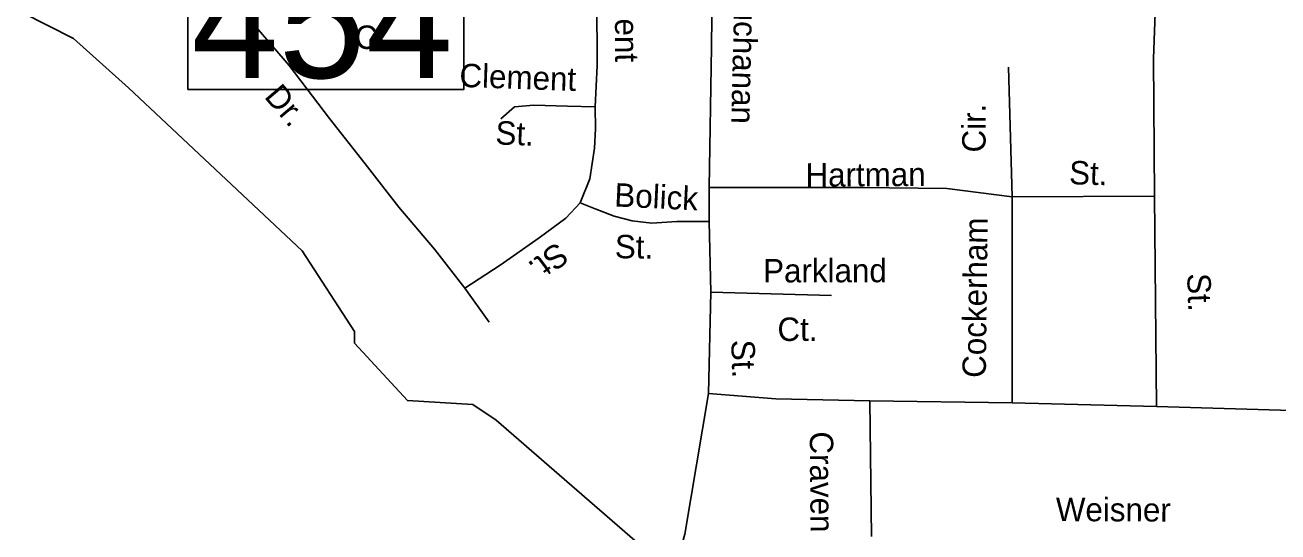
# Model space of a CAD drawing. Extents: x 1551653 to 1702041, y 811336 to 920032.
# Drawn here: x 1628058 to 1631566, y 842302 to 843721 of the extents above; entities that cross this region are included whole.
import ezdxf

# ---------------------------------------------------------------- set-up
doc = ezdxf.new("R2010")
doc.units = 0
for name, color, linetype in [('Old_Level_10', 7, 'Continuous'), ('Old_Level_31', 7, 'Continuous'), ('Old_Level_35', 7, 'Continuous'), ('Old_Level_59', 7, 'Continuous')]:
    doc.layers.add(name, color=color, linetype=linetype)

msp = doc.modelspace()

# ---------------------------------------------------------------- linework, layer by layer
at = {"layer": 'Old_Level_31'}
msp.add_lwpolyline([(1628514.011, 843909.718), (1629286.946, 843909.718), (1629286.946, 843540.573), (1628514.011, 843540.573), (1628514.011, 843909.718)], dxfattribs=at)
at = {"layer": 'Old_Level_35'}
for p, q in [((1630811.709, 843603.048), (1630822.146, 843240.118)), ((1629973.936, 843265.908), (1629973.936, 843170.456)), ((1631220.942, 843241.89), (1630822.146, 843240.118)), ((1630822.146, 843240.118), (1630822.146, 842663.086)), ((1631220.942, 843241.89), (1631226.827, 842652.777)), ((1629973.936, 843170.456), (1629978.478, 842972.733)), ((1629289.34, 842984.266), (1629357.851, 842889.224)), ((1629978.478, 842972.733), (1629972.071, 842689.655)), ((1629978.478, 842972.733), (1630316.803, 842963.643)), ((1630822.146, 842663.086), (1630423.788, 842668.615)), ((1630423.788, 842668.615), (1630427.939, 842289.151)), ((1631226.827, 842652.777), (1630822.146, 842663.086))]:
    msp.add_line(p, q, dxfattribs=at)
for points in [[(1631306.723, 844441.237), (1631254.718, 844311.16), (1631233.844, 844060.503), (1631218.19, 843627.076), (1631220.942, 843241.89)], [(1629663.72, 844087.889), (1629660.373, 843991.902), (1629659.359, 843794.012), (1629660.389, 843608.09), (1629654.638, 843492.342)], [(1629985.29, 844078.246), (1629980.748, 843660.074), (1629973.936, 843265.908)], [(1628550.243, 844054.865), (1628567.179, 843936.226), (1628594.275, 843854.873), (1628631.533, 843804.027), (1628665.756, 843760.941), (1628797.31, 843607.188), (1628910.978, 843459.603), (1629010.847, 843332.106), (1629105.033, 843210.729), (1629205.108, 843093.432), (1629289.34, 842984.266)], [(1629654.638, 843492.342), (1629576.82, 843493.52), (1629482.837, 843496.827), (1629428.904, 843491.719), (1629390.406, 843458.281)], [(1629654.638, 843492.342), (1629655.78, 843430.282), (1629652.889, 843376.513), (1629639.743, 843290.732), (1629612.558, 843223.245)], [(1629973.936, 843265.908), (1630398.546, 843265.908), (1630639.234, 843263.635), (1630822.146, 843240.118)], [(1629289.34, 842984.266), (1629388.3, 843048.695), (1629497.306, 843124.928), (1629572.056, 843179.843), (1629612.558, 843223.245)], [(1629612.558, 843223.245), (1629654.445, 843206.585), (1629708.05, 843185.686), (1629757.82, 843173.071), (1629813.509, 843166.139), (1629883.647, 843171.119), (1629973.936, 843170.456)], [(1629972.071, 842689.655), (1629905.451, 842295.18), (1629802.746, 841928.486), (1629744.453, 841720.135), (1629636.197, 841517.342), (1629534.011, 841383.711), (1629450.736, 841294.815), (1629361.91, 841230.921), (1629256.429, 841155.915), (1629148.172, 841058.685), (1629074.232, 840958.229)], [(1629972.071, 842689.655), (1630160.173, 842674.135), (1630423.788, 842668.615)], [(1632385.28, 842629.31), (1631986.622, 842631.657), (1631637.21, 842641.043), (1631226.827, 842652.777)]]:
    msp.add_lwpolyline(points, dxfattribs=at)
at = {"layer": 'Old_Level_59'}
for points in [[(1629377.791, 842615.042), (1629311.764, 842659.025), (1629128.755, 842669.381), (1628980.81, 842829.936), (1628980.81, 842862.745), (1628833.788, 843088.917), (1628347.814, 843545.261), (1628194.141, 843682.91), (1627906.967, 843829.064), (1627480.777, 843939.956), (1627148.828, 844132.132), (1626891.73, 844063.731)], [(1630570.066, 840506.44), (1630486.815, 840718.208), (1630466.822, 841119.084), (1630403.769, 841419.024), (1630183.851, 841781.351), (1629814.757, 842235.234), (1629377.791, 842615.042)]]:
    msp.add_lwpolyline(points, dxfattribs=at)

# ---------------------------------------------------------------- texts
at = {"layer": 'Old_Level_10'}
for s, rotation, p in [('Clement', 270.317469, (1629708.897, 843943.81)), ('Buchanan', 268.610667, (1630045.154, 843839.85)), ('Ct.', 359.876581, (1628981.447, 843654.116)), ('Clement', 357.984697, (1629273.689, 843547.77)), ('Dr.', 310.470247, (1628725.771, 843519.558)), ('Cir.', 89.930389, (1630747.862, 843364.109)), ('St.', 357.984697, (1629374.583, 843386.866)), ('St.', 358.379758, (1630981.095, 843275.341)), ('Hartman', 0.300303, (1630243.713, 843268.544)), ('Bolick', 357.232975, (1629707.152, 843213.203)), ('Cockerham', 89.31545, (1630748.395, 842732.973)), ('St.', 359.221406, (1629709.436, 843068.219)), ('St.', 216.846428, (1629547.491, 843116.294)), ('Parkland', 0.1233, (1630125.02, 843000.237)), ('St.', 271.776811, (1631312.245, 843025.204)), ('Ct.', 0.123297, (1630165.039, 842836.428)), ('St.', 271.657894, (1630035.564, 842838.95)), ('Craven', 270.498644, (1630255.365, 842582.998)), ('Weisner', 359.754956, (1630944.457, 842332.179))]:
    msp.add_text(s, height=65.6167, rotation=rotation, dxfattribs=at).set_placement(p)
at = {"layer": 'Old_Level_31'}
msp.add_text('454', height=328.0833, dxfattribs=at).set_placement((1628523.992, 843572.7))

doc.saveas('drawing.dxf')
